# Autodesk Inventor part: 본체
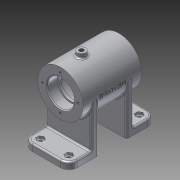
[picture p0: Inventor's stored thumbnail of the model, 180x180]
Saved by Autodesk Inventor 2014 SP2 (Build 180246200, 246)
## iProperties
Created: 2017-02
Part Number: 본체
Material: 알루미늄 6061
Document SubType Name: Modeling
Designer: 거성
Density: 2.71 g/cm^3
Appearance: 알루미늄 - 평지
Author: 거성
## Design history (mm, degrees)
sketch "스케치1"
  geometry: C1 r 27 at (0, 0); 2 further points
  constraints: 2 coincident, 1 centre point
  dimensions: "d8" = 54 diameter of C1
extrude "돌출1" new body sketch "스케치1" stored distance "d9" = 70; taper "d10" = 0 deg
sketch "스케치2"
  geometry: C1 r 27 at (0, 0) reference; C2 r 16 at (0, 0)
  constraints: 1 centre point, 1 coincident
  dimensions: "d11" = 32 diameter of C2
extrude "돌출2" cut sketch "스케치2" distance "d12" = 12; taper "d13" = 0 deg
sketch "스케치3"
  geometry: C1 r 16 at (0, 0) reference; C2 r 14 at (0, 0)
  constraints: 1 centre point, 1 coincident
  dimensions: "d14" = 28 diameter of C2
extrude "돌출3" cut sketch "스케치3" distance "d15" = 3; taper "d16" = 0 deg
sketch "스케치4"
  geometry: C1 r 14 at (0, 0) reference; C2 r 22 at (0, 0)
  constraints: 1 centre point, 1 coincident
  dimensions: "d17" = 44 diameter of C2
extrude "돌출4" cut sketch "스케치4" distance "d18" = 40; taper "d19" = 0 deg
sketch "스케치5"
  geometry: C1 r 27 at (0, 0) reference; C2 r 16 at (0, 0)
  constraints: 1 centre point, 1 coincident
  dimensions: "d20" = 32 diameter of C2
extrude "돌출5" cut sketch "스케치5" distance "d21" = 12; taper "d22" = 0 deg
sketch "스케치6"
  geometry: C1 r 16 at (0, 0) reference; C2 r 14 at (0, 0)
  constraints: 1 centre point, 1 coincident
  dimensions: "d23" = 28 diameter of C2
extrude "돌출6" cut sketch "스케치6" distance "d24" = 3; taper "d25" = 0 deg
node "작업 평면1"
sketch "스케치7"
  geometry: L1 (27, -52)-(-27, -52); L2 (-27, -52)-(-27, -17); L3 (-27, -17)-(27, -17); L4 (27, -17)-(27, -52); 2 further points
  constraints: 8 end point, 2 parallel, 1 horizontal, 1 midpoint, 1 perpendicular, 1 vertical alignment
  dimensions: "d27" = 17 distance from line of L3 point (0, 0); "d28" = 52 distance from line of L1 point (0, 0); "d29" = 54 distance between parallel lines of L2 L4
extrude "돌출7" join sketch "스케치7" distance "d30" = 8; taper "d31" = 0 deg
sketch "스케치8"
  geometry: L1 (-27, 52)-(-27, 17) reference; L2 (-27, 25)-(27, 25); L3 (27, 25)-(27, 17); L4 (27, 17)-(-27, 17); L5 (-27, 17)-(-27, 25); 1 further point
  constraints: 8 end point, 2 parallel, 1 horizontal, 1 perpendicular, 1 point on line
  dimensions: "d32" = 8 distance between parallel lines of L2 L4
extrude "돌출8" join sketch "스케치8" stored distance "d33" = 8; taper "d34" = 0 deg
fillet "모깎기1" dims "d35" = 10
node "작업 평면2"
fillet "모깎기2" dims "d37" = 10
node "작업 평면3"
sketch "스케치9"
  geometry: L1 (27, 35)-(-27, 35) reference; C1 r 5 at (0, 10); 1 further point
  constraints: 1 centre point, 1 vertical alignment
  dimensions: "d39" = 10 diameter of C1; "d40" = 25 distance from line of L1 C1.centre
extrude "돌출9" join sketch "스케치9" stored distance "d41" = 8; taper "d42" = 0 deg
node "작업 평면4"
sketch "스케치10"
  geometry: L1 (0, 0)-(-16.339, -25.16); L2 (0, 0)-(30, 0)
  constraints: 4 end point, 1 equal length, 1 horizontal
  dimensions: "d44" = 30 distance of L1.start L1.end; "d45" = 123 deg angle of L1 L2
node "작업 평면5"
sketch "스케치11"
  geometry: C1 r 6 at (0, 0); 1 further point
  constraints: 1 centre point, 1 coincident
  dimensions: "d46" = 12 diameter of C1
extrude "돌출10" join sketch "스케치11" stored distance "d47" = 8; taper "d48" = 0 deg
sketch "스케치12"
  geometry: L1 (10, -21.5)-(6.103, -19.25); L2 (6.103, -19.25)-(6.103, -14.75); L3 (6.103, -14.75)-(10, -12.5); L4 (10, -12.5)-(13.897, -14.75); L5 (13.897, -14.75)-(13.897, -19.25); L6 (13.897, -19.25)-(10, -21.5); L7 (44, -12.5)-(47.897, -14.75); L8 (47.897, -14.75)-(47.897, -19.25); L9 (47.897, -19.25)-(44, -21.5); L10 (44, -21.5)-(40.103, -19.25); L11 (40.103, -19.25)-(40.103, -14.75); L12 (40.103, -14.75)-(44, -12.5); A1 r 10 centre (10, -17) between (0, -17) and (10, -27) reference; A2 r 10 centre (44, -17) between (44, -27) and (54, -17) reference; 3 further points
  constraints: 24 end point, 2 coincident, 2 vertical alignment, 26 other
  dimensions: "d49" = 9 distance of L1.start L3.end; "d50" = 9 distance of L7.start L9.end
extrude "돌출11" cut sketch "스케치12" distance "d51" = 3; taper "d52" = 0 deg
sketch "스케치13"
  geometry: C1 r 2.5 at (10, -17); C2 r 2.5 at (44, -17); A1 r 10 centre (10, -17) between (0, -17) and (10, -27) reference; A2 r 10 centre (44, -17) between (44, -27) and (54, -17) reference; 1 further point
  constraints: 2 centre point, 2 coincident
  dimensions: "d53" = 5 diameter of C1; "d54" = 5 diameter of C2
extrude "돌출12" cut sketch "스케치13" stored distance "d55" = 3; taper "d56" = 0 deg
sketch "스케치14" dims "d57" = 42
  geometry: L1 (0, 0)-(0, 21); C1 r 27 at (0, 0) reference
  constraints: 2 end point, 1 coincident, 1 vertical, 1 vertical alignment, 2 other
hole "구멍1" sketch "스케치14" at (0, 21) diameter "d58" = 3.242; stored, may be unused: countersink angle "d62" = 90 deg, drill point angle "d64" = 118 deg; dims "d59" = 8, "d60" = 4, "d61" = 2, "d63" = 10
hole "구멍2" diameter "d70" = 5.188; stored, may be unused: countersink angle "d74" = 90 deg, drill point angle "d76" = 118 deg; dims "d68" = 10, "d69" = 10, "d71" = 19, "d72" = 4, "d73" = 2, "d75" = 20
hole "구멍3" diameter "d79" = 5.188; stored, may be unused: countersink angle "d83" = 90 deg, drill point angle "d85" = 118 deg; dims "d77" = 10, "d78" = 10, "d80" = 19, "d81" = 4, "d82" = 2, "d84" = 20
fillet "모깎기3" dims "d86" = 2
node "작업 평면6"
sketch "스케치15"
  geometry: L1 (27, 35)-(-27, 35) reference; L2 (27, -35)-(27, 35) reference; 2 further points
  constraints: 1 other
  dimensions: "d87" = 35 distance from line of L1 point (0, 0); "d88" = 27 distance from line of L2 point (0, 0)
feature "엠보싱1" sketch "스케치15" dims "d8" = 54, "d17" = 44, "d89" = 0.5, "d90" = 0
chamfer "모따기1" distance "d91" = 1; stored, may be unused: second distance "d92" = 2, angle "d93" = 45 deg
fillet "모깎기4" dims "d94" = 3
fillet "모깎기5" dims "d95" = 0.3
node "솔리드1"
mirror "대칭1"
mirror "대칭2"
pattern_circular "원형 패턴1" dims angle "d66" = 360 deg
mirror "대칭3"
other parameters: "d36" = 0, "d38" = 32, "d43" = -35
